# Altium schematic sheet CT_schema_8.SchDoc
size 287 x 160 mm
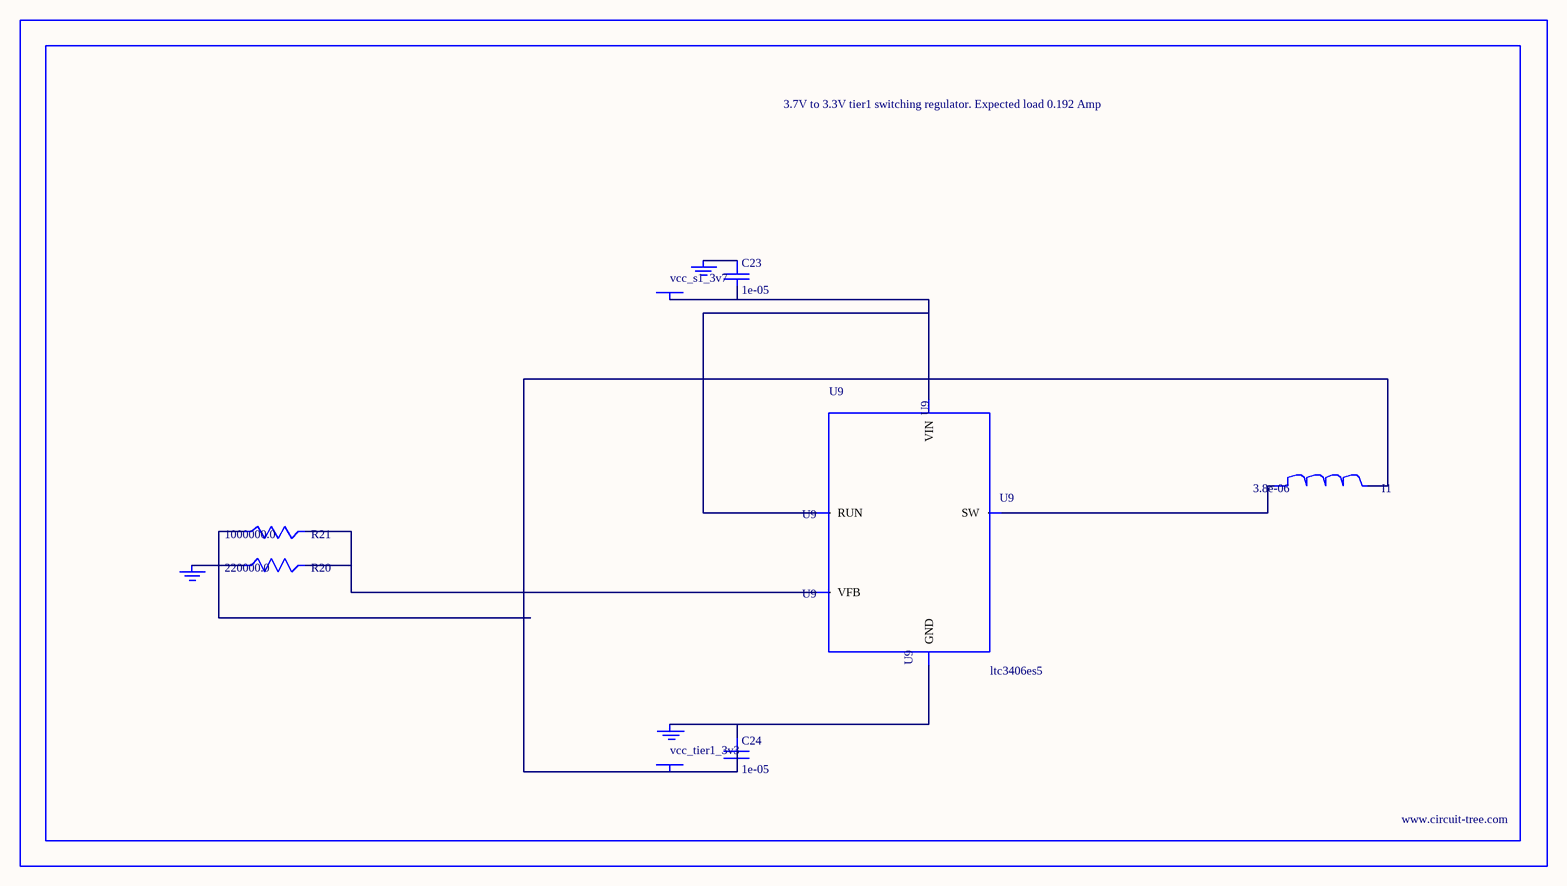
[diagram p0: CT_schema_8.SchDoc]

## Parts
BORDER7  (no value)
C23  1e-05  [C0805]
C24  1e-05  [C0805]
GND_INSTANCE_7_0  (no value)
GND_INSTANCE_7_1  (no value)
GND_INSTANCE_7_2  (no value)
I1  3.8e-06  [DR1040]
POWER_INSTANCE_7_0  vcc_tier1_3v3
POWER_INSTANCE_7_1  vcc_s1_3v7
R20  220000.0  [R0603]
R21  1000000.0  [R0603]
U9  ltc3406es5  [TSOT-23-5]

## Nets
NetC23_1: C23.1 GND_INSTANCE_7_1.0(GND)
NetC23_2: C23.2 POWER_INSTANCE_7_1.0(PWR) U9.1(RUN) U9.4(VIN)
NetC24_1: C24.1 GND_INSTANCE_7_0.0(GND) U9.2(GND)
NetC24_2: C24.2 I1.2 POWER_INSTANCE_7_0.0(PWR) R21.1
NetGND_INSTANCE_7_2_0: GND_INSTANCE_7_2.0(GND) R20.1
NetI1_1: I1.1 U9.3(SW)
NetR20_2: R20.2 R21.2 U9.5(VFB)

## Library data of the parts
BORDER7 = BORDER_PAGE7
C23 C24 = C0805C106K8RACTU
GND_INSTANCE_7_0-GND_INSTANCE_7_2 = GND
I1 = DR1040-3R8-R
POWER_INSTANCE_7_0 POWER_INSTANCE_7_1 = PWR
R20 = RC0603JR-07220KL
R21 = RC0603JR-071ML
